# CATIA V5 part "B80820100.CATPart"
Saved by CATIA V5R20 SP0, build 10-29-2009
Part number: B80820100
Revision: 3
Definition: design
Nomenclature: B80820100
Source: made
Description: NOT SPECIFIED
Bounding box of the stored display mesh (mm): x -11.818 to 11.818, y -12 to 12, z 0 to 100
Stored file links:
  C:\Users\Raffaele\Desktop\3D X SITO CF\BOLEX\4-PILLAR REF 808\B80820100.CATPart
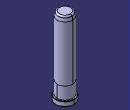
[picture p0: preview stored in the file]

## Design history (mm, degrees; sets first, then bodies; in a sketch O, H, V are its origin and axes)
Body1 "MANIFOLD_SOLID_BREP #450" (main body)
  Solid1: solid without history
